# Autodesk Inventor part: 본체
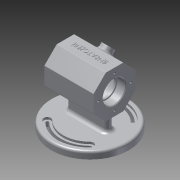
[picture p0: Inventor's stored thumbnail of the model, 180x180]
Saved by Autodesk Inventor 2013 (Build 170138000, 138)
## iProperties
Created: 2017-04
Part Number: 본체
Material: 알루미늄 6061
Document SubType Name: Modeling
Designer: Administrator
Density: 2.71 g/cm^3
Mass: 562.526 g
Surface Area: 565.55 cm^2
Volume: 207.574 cm^3
Author: Administrator
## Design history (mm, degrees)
sketch "스케치1"
  geometry: C1 r 55 at (0, 0); 1 further point
  constraints: 1 centre point, 1 coincident
  dimensions: "d0" = 110 diameter of C1
extrude "돌출1" new body sketch "스케치1" distance "d2" = 10; taper "d3" = 0 deg
sketch "스케치2"
  geometry: L1 (0, 0)-(0, 48); L2 (-48.451, 0)-(48.451, 0); L3 (0, 0)-(-33.941, 33.941); L4 (0, 0)-(33.941, 33.941); L5 (-33.941, 33.941)-(-26.87, 26.87); L6 (26.87, 26.87)-(33.941, 33.941); A1 r 48 centre (0, 0) between (33.941, 33.941) and (-33.941, 33.941); A2 r 38 centre (0, 0) between (26.87, 26.87) and (-26.87, 26.87); 3 further points
  constraints: 12 end point, 7 point on circle, 4 point on line, 3 coincident, 2 centre point, 2 perpendicular, 1 midpoint, 1 vertical, 10 other
  dimensions: "d6" = 45 deg angle of L1 L3; "d7" = 48 radius of A1; "d9" = 38 radius of A2
extrude "돌출2" cut sketch "스케치2" distance "d10" = 3; taper "d11" = 0 deg
sketch "스케치9"
  geometry: A1 r 48 centre (0, 0) between (33.941, 33.941) and (-33.941, 33.941) reference; A2 r 5 centre (-30.406, 30.406) between (-33.941, 33.941) and (-26.87, 26.87) reference; A3 r 38 centre (0, 0) between (26.87, 26.87) and (-26.87, 26.87) reference; A4 r 5 centre (30.406, 30.406) between (26.87, 26.87) and (33.941, 33.941) reference; A5 r 45 centre (0, 0) between (31.82, 31.82) and (-31.82, 31.82); A6 r 2 centre (30.406, 30.406) between (28.991, 28.991) and (31.82, 31.82); A7 r 41 centre (0, 0) between (28.991, 28.991) and (-28.991, 28.991); A8 r 2 centre (-30.406, 30.406) between (-31.82, 31.82) and (-28.991, 28.991); 1 further point
  constraints: 8 point on circle, 4 centre point, 3 other
  dimensions: "d62" = 2 radius of A8
extrude "돌출7" cut sketch "스케치9" distance "d64" = 7; taper "d65" = 0 deg
sketch "스케치3"
  geometry: L1 (35, 78)-(23, 78); L2 (23, 78)-(23, 76); L3 (23, 76)-(20, 76); L4 (20, 76)-(20, 87); L5 (20, 87)-(-20, 87); L6 (-20, 87)-(-20, 76); L7 (-20, 76)-(-23, 76); L8 (-23, 76)-(-23, 78); L9 (-23, 78)-(-35, 78); L10 (-35, 78)-(-35, 92); L11 (-35, 92)-(35, 92); L12 (35, 92)-(35, 78); L13 (-35, 62)-(35, 62); 2 further points
  constraints: 26 end point, 9 parallel, 3 vertical alignment, 1 collinear, 1 horizontal, 1 midpoint, 1 perpendicular, 1 vertical
  dimensions: "d13" = 70 distance of L13.start L13.end; "d14" = 60 diameter of L11 L13; "d15" = 32 diameter of L9 L13; "d16" = 28 diameter of L7 L13; "d17" = 50 diameter of L5 L13; "d18" = 28 diameter of L3 L13; "d19" = 32 diameter of L1 L13; "d20" = 12 distance of L8.end L9.end; "d21" = 3 distance of L6.end L7.end; "d22" = 40 distance of L4.end L5.end; "d23" = 3 distance of L2.end L3.end; "d66" = 124 diameter of point (0, 0) L13
revolve "회전1" sketch "스케치3" stored, may be unused: angle "d24" = 90 deg
sketch "스케치4"
  geometry: L1 (12.426, 30)-(30, 12.426); L2 (30, 12.426)-(30, -12.426); L3 (30, -12.426)-(12.426, -30); L4 (12.426, -30)-(-12.426, -30); L5 (-12.426, -30)-(-30, -12.426); L6 (-30, -12.426)-(-30, 12.426); L7 (-30, 12.426)-(-12.426, 30); L8 (-12.426, 30)-(12.426, 30); 4 further points
  constraints: 16 end point, 2 vertical alignment, 1 coincident, 1 midpoint, 18 other
extrude "돌출3" join sketch "스케치4" distance "d25" = 70; taper "d26" = 0 deg
sketch "스케치5"
  geometry: L1 (-24, 5)-(24, 5); L2 (24, 5)-(24, -5); L3 (24, -5)-(-24, -5); L4 (-24, -5)-(-24, 5); L5 (24, -5)-(-24, 5); 4 further points
  constraints: 10 end point, 3 midpoint, 2 parallel, 2 vertical alignment, 1 coincident, 1 horizontal, 1 perpendicular, 4 other
  dimensions: "d27" = 48 distance of L1.start L1.end; "d29" = 10 distance of L1.end L2.end
extrude "돌출4" join sketch "스케치5" stored distance "d30" = 70; taper "d31" = 0 deg
fillet "모깎기1" dims "d32" = 5
chamfer "모따기2" distance "d57" = 1; stored, may be unused: second distance "d58" = 2, angle "d59" = 45 deg
fillet "모깎기2" dims "d60" = 0.3
fillet "모깎기3" dims "d61" = 3
fillet "모깎기4" dims "d67" = 3
sketch "스케치11"
  geometry: L1 (70, 0)-(70, 24.853) reference; C1 r 8 at (35, 12.426); 2 further points
  constraints: 1 centre point, 1 horizontal alignment, 1 midpoint, 1 vertical alignment
  dimensions: "d72" = 16 diameter of C1
extrude "돌출8" join sketch "스케치11" distance "d74" = 7; taper "d75" = 0 deg
fillet "모깎기7" dims "d76" = 3
sketch "스케치12"
  geometry: C1 r 8 at (0, 0) reference; C2 r 4 at (0, 0); 1 further point
  constraints: 1 centre point, 1 coincident
  dimensions: "d77" = 8 diameter of C2
extrude "돌출9" cut sketch "스케치12" stored distance "d79" = 7; taper "d80" = 0 deg
chamfer "모따기3" distance "d81" = 1; stored, may be unused: second distance "d82" = 2, angle "d83" = 45 deg
sketch "스케치13"
  geometry: L1 (0, 0)-(-70, 0); L2 (-70, 0)-(-70, 24.853); L3 (-70, 24.853)-(0, 24.853); L4 (0, 24.853)-(0, 0); L5 (0, 0)-(0, 24.853) reference; L6 (0, 24.853)-(-70, 24.853) reference; 2 further points
  constraints: 3 coincident, 2 collinear, 2 other
feature "엠보싱2" sketch "스케치13" dims "d2" = 10, "d3" = 0, "d13" = 70, "d14" = 60, "d15" = 32, "d16" = 28, "d17" = 50, "d18" = 28, "d19" = 32, "d20" = 12, "d21" = 3, "d22" = 40, "d23" = 3, "d66" = 124, "d84" = 0.5, "d85" = 0
sketch "스케치14" dims "d86" = 46
  geometry: L1 (0, 0)-(-17.574, -17.574) reference; L2 (0, 24.853)-(0, 0) reference; L3 (-17.574, 42.426)-(0, 24.853) reference; L4 (-42.426, 42.426)-(-17.574, 42.426) reference; L5 (-60, 24.853)-(-42.426, 42.426) reference; L6 (-60, 0)-(-60, 24.853) reference; L7 (-42.426, -17.574)-(-60, 0) reference; L8 (-17.574, -17.574)-(-42.426, -17.574) reference; C1 r 17 at (-30, 12.426) reference; 3 further points
  constraints: 2 vertical alignment, 1 coincident, 2 other
hole "구멍2" sketch "스케치14" at (-30, 35.426) diameter "d88" = 3.242; stored, may be unused: countersink angle "d92" = 82 deg, drill point angle "d94" = 118 deg; dims "d89" = 8, "d90" = 3.023, "d91" = 2, "d93" = 10
fillet "모깎기8" dims "d98" = 1
node "솔리드1"
mirror "대칭1"
pattern_circular "원형 패턴2" dims angle "d96" = 360 deg
mirror "대칭3"
node "투영된 루프3"
node "투영된 루프4"
node "투영된 루프5"
other parameters: "d4" = 96, "d5" = 76
